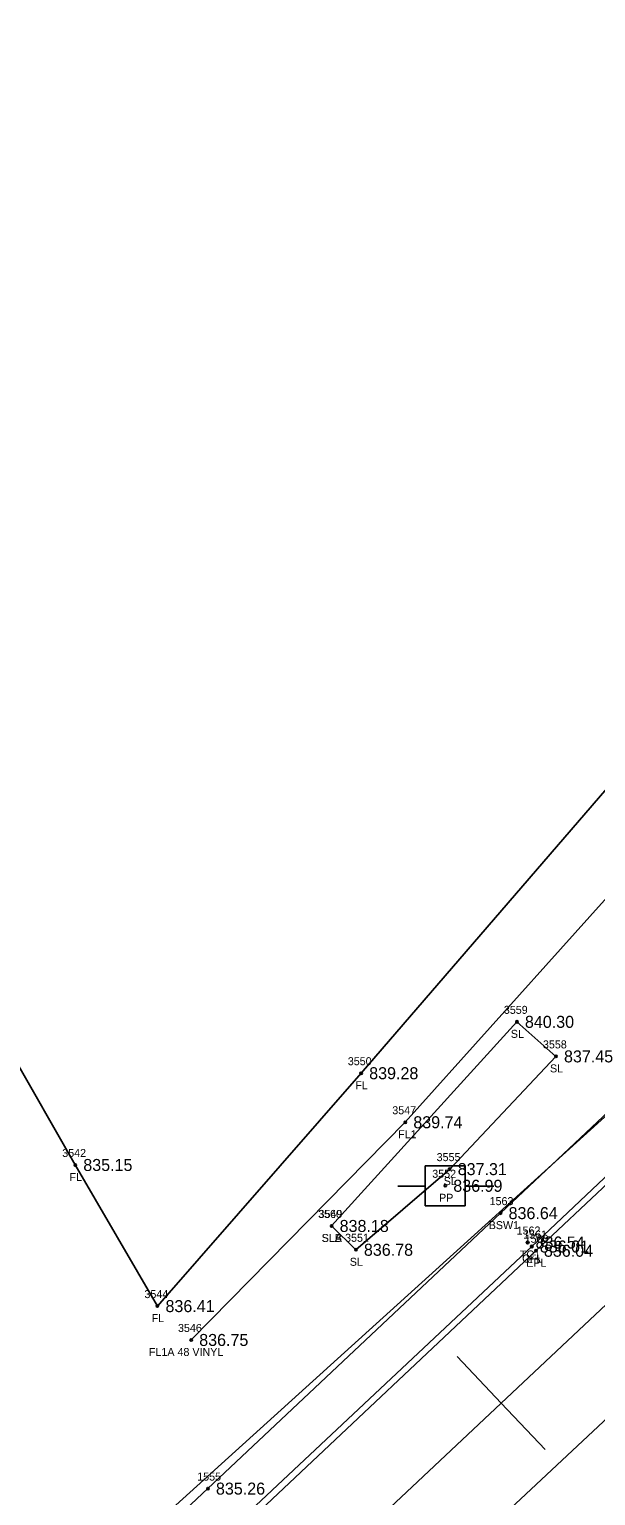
# Model space of a CAD drawing. Extents: x 1622501 to 1626664, y 1117816 to 1121579.
# Drawn here: x 1624658.9 to 1624729.6, y 1119930.4 to 1120113.7 of the extents above; entities that cross this region are included whole.
import ezdxf

# ---------------------------------------------------------------- set-up
doc = ezdxf.new("R2010")
doc.units = 0
for name, color, linetype in [('RD_EX_Conc', 7, 'Continuous'), ('RD_EX_Conc_txCode', 7, 'Continuous'), ('RD_EX_DR_Pipe', 7, 'Continuous'), ('RD_EX_Fence_Other', 7, 'Continuous'), ('RD_EX_Fence_Other_txCode', 7, 'Continuous'), ('RD_EX_Road', 7, 'Continuous'), ('RD_EX_Road_txCode', 7, 'Continuous'), ('RD_EX_TX_Conc_ELEV', 7, 'Continuous'), ('RD_EX_TX_Fence_Other_ELEV', 7, 'Continuous'), ('RD_EX_TX_Road_ELEV', 7, 'Continuous'), ('RD_EX_TX_VEG_ELEV', 7, 'Continuous'), ('RD_EX_UT', 7, 'Continuous'), ('RD_EX_UT_txCode', 7, 'Continuous'), ('RD_EX_VEG', 7, 'Continuous'), ('RD_EX_VEG_txCode', 7, 'Continuous'), ('RD_HC_Cl', 7, 'Continuous'), ('RD_HC_Data_Tic', 7, 'Continuous'), ('RD_HC_Survey_ELEV', 7, 'Continuous'), ('RD_SMD_Locator', 7, 'Continuous')]:
    doc.layers.add(name, color=color, linetype=linetype)

msp = doc.modelspace()

# ---------------------------------------------------------------- linework, layer by layer
at = {"layer": 'RD_EX_Conc'}
for points in [[(1624627.29, 1119872.79), (1624648.82, 1119893.33), (1624685.14, 1119927.24), (1624721.63, 1119961.54), (1624757.72, 1119995.68), (1624794.23, 1120030.2), (1624818.18, 1120052.72), (1624821.97, 1120057.48), (1624824.89, 1120062.27)], [(1624660.88, 1119912.17), (1624681.2, 1119931.28), (1624717.73, 1119965.71), (1624754.02, 1119999.93), (1624790.62, 1120034.43), (1624814.46, 1120056.83)]]:
    msp.add_lwpolyline(points, dxfattribs=at)
at = {"layer": 'RD_EX_DR_Pipe'}
msp.add_lwpolyline([(1625495.16, 1120700.17), (1625478.48, 1120693.94), (1625478.48, 1120693.94), (1625401.27, 1120618.61), (1625386.85, 1120595.89), (1625386.85, 1120595.89), (1625239.34, 1120454.58), (1625067.49, 1120292.51), (1624913.32, 1120147.08), (1624906.32, 1120142.58), (1624803.57, 1120043.73), (1624612.21, 1119870.34), (1624528.3, 1119793.12)], dxfattribs=at)
at = {"layer": 'RD_EX_Fence_Other'}
for points in [[(1624679.11, 1119949.86), (1624705.84, 1119977.07), (1624737.67, 1120012.59), (1624752.13, 1120029.37), (1624792.98, 1120063.53), (1624804.63, 1120073.99)], [(1624641.35, 1120014.22), (1624648.5, 1119999.9), (1624664.64, 1119971.73), (1624674.9, 1119954.09), (1624700.33, 1119983.2), (1624731.77, 1120019.72), (1624746.64, 1120034.86), (1624764.66, 1120053.21), (1624771.87, 1120060.24), (1624771.87, 1120060.24), (1624761.47, 1120072.27)]]:
    msp.add_lwpolyline(points, dxfattribs=at)
at = {"layer": 'RD_EX_Road'}
for points in [[(1624481.69, 1119706.57), (1624518.07, 1119740.62), (1624554.52, 1119774.63), (1624590.99, 1119808.78), (1624627.13, 1119843.17), (1624664.12, 1119876.78), (1624700.28, 1119911.28), (1624736.97, 1119945.68), (1624773.63, 1119979.8), (1624810.11, 1120014.45), (1624846.42, 1120048.91), (1624882.77, 1120083.19), (1624919.14, 1120117.14), (1624955.41, 1120151.75), (1624991.66, 1120186.11), (1625027.75, 1120220.09), (1625065.42, 1120252.96), (1625104.19, 1120284.12), (1625143.2, 1120315.04), (1625181.69, 1120345.9), (1625220.31, 1120377.13)], [(1624468.78, 1119721.97), (1624504.42, 1119755.42), (1624540.92, 1119789.52), (1624577, 1119823.63), (1624614.11, 1119858.36), (1624622.03, 1119866.66), (1624623.94, 1119868.41), (1624624.9, 1119868.05), (1624628.91, 1119871.9), (1624628.36, 1119872.68), (1624649.22, 1119892.43), (1624685.62, 1119926.57), (1624722.14, 1119961.01), (1624758.27, 1119995), (1624794.85, 1120029.55), (1624818.75, 1120051.93), (1624828.77, 1120068.77), (1624829.58, 1120080.91), (1624828.33, 1120088.31), (1624824.85, 1120095.34), (1624817.99, 1120105.91), (1624780.84, 1120159.39), (1624775.47, 1120165.89), (1624755.05, 1120187.38)]]:
    msp.add_lwpolyline(points, dxfattribs=at)
at = {"layer": 'RD_EX_UT'}
for p, q in [((1624713.32, 1119971.64), (1624708.32, 1119971.64)), ((1624708.32, 1119971.64), (1624708.32, 1119966.64)), ((1624713.32, 1119966.64), (1624713.32, 1119971.64)), ((1624704.89, 1119969.08), (1624708.36, 1119969.08)), ((1624713.25, 1119969.08), (1624716.89, 1119969.08)), ((1624708.32, 1119966.64), (1624713.32, 1119966.64))]:
    msp.add_line(p, q, dxfattribs=at)
at = {"layer": 'RD_EX_VEG'}
msp.add_lwpolyline([(1624696.64, 1119964.11), (1624699.67, 1119961.13), (1624711.38, 1119971.21), (1624724.65, 1119985.3), (1624719.77, 1119989.62), (1624696.64, 1119964.11)], dxfattribs=at)
at = {"layer": 'RD_HC_Cl'}
msp.add_line((1624678.65, 1119905.11), (1624870.49, 1120085.68), dxfattribs=at)
at = {"layer": 'RD_HC_Data_Tic'}
for q in [(1624712.33, 1119947.8), (1624723.3, 1119936.15)]:
    msp.add_line((1624717.81, 1119941.97), q, dxfattribs=at)
at = {"layer": 'RD_SMD_Locator'}
for centre in [(1624719.77, 1119989.62), (1624724.65, 1119985.3), (1624700.33, 1119983.2), (1624705.84, 1119977.07), (1624664.64, 1119971.73), (1624711.38, 1119971.21), (1624710.83, 1119969.13), (1624717.73, 1119965.71), (1624696.64, 1119964.11), (1624696.64, 1119964.11), (1624699.67, 1119961.13), (1624721.1, 1119962.04), (1624721.63, 1119961.54), (1624722.14, 1119961.01), (1624674.9, 1119954.09), (1624679.11, 1119949.86), (1624681.2, 1119931.28)]:
    msp.add_circle(centre, 0.15, dxfattribs=at)

# ---------------------------------------------------------------- texts
at = {"layer": 'RD_EX_Conc_txCode'}
for s, p in [('1563', (1624716.36, 1119966.71)), ('BSW1', (1624716.25, 1119963.71)), ('1562', (1624719.73, 1119963.04)), ('1561', (1624720.55, 1119962.54)), ('TC1', (1624720.14, 1119960.04)), ('CFL', (1624720.43, 1119959.54)), ('1555', (1624679.86, 1119932.28))]:
    msp.add_text(s, height=1, dxfattribs=at).set_placement(p)
at = {"layer": 'RD_EX_Fence_Other_txCode'}
for s, p in [('3550', (1624698.66, 1119984.2)), ('FL', (1624699.6, 1119981.2)), ('3547', (1624704.21, 1119978.07)), ('FL1', (1624704.94, 1119975.07)), ('3542', (1624663.01, 1119972.73)), ('FL', (1624663.91, 1119969.73)), ('3544', (1624673.27, 1119955.09)), ('FL', (1624674.17, 1119952.09)), ('3546', (1624677.46, 1119950.86)), ('FL1A 48 VINYL', (1624673.83, 1119947.86))]:
    msp.add_text(s, height=1, dxfattribs=at).set_placement(p)
at = {"layer": 'RD_EX_Road_txCode'}
for s, p in [('1560', (1624720.73, 1119962.01)), ('EPL', (1624720.94, 1119959.01))]:
    msp.add_text(s, height=1, dxfattribs=at).set_placement(p)
at = {"layer": 'RD_EX_TX_Conc_ELEV'}
for s, p in [('836.64', (1624718.73, 1119964.96)), ('836.54', (1624722.1, 1119961.29)), ('836.01', (1624722.63, 1119960.79)), ('835.26', (1624682.2, 1119930.53))]:
    msp.add_text(s, height=1.5, dxfattribs=at).set_placement(p)
at = {"layer": 'RD_EX_TX_Fence_Other_ELEV'}
for s, p in [('839.28', (1624701.33, 1119982.45)), ('839.74', (1624706.84, 1119976.32)), ('835.15', (1624665.64, 1119970.98)), ('836.41', (1624675.9, 1119953.34)), ('836.75', (1624680.11, 1119949.11))]:
    msp.add_text(s, height=1.5, dxfattribs=at).set_placement(p)
at = {"layer": 'RD_EX_TX_Road_ELEV'}
msp.add_text('836.04', height=1.5, dxfattribs=at).set_placement((1624723.14, 1119960.26))
at = {"layer": 'RD_EX_TX_VEG_ELEV'}
for s, p in [('840.30', (1624720.77, 1119988.87)), ('837.45', (1624725.65, 1119984.55)), ('837.31', (1624712.38, 1119970.46)), ('838.18', (1624697.64, 1119963.36)), ('838.18', (1624697.64, 1119963.36)), ('836.78', (1624700.67, 1119960.38))]:
    msp.add_text(s, height=1.5, dxfattribs=at).set_placement(p)
at = {"layer": 'RD_EX_UT_txCode'}
for s, p in [('3552', (1624709.2, 1119970.13)), ('PP', (1624710.05, 1119967.13))]:
    msp.add_text(s, height=1, dxfattribs=at).set_placement(p)
at = {"layer": 'RD_EX_VEG_txCode'}
for s, p in [('3559', (1624718.14, 1119990.62)), ('SL', (1624719.01, 1119987.62)), ('3558', (1624723.02, 1119986.3)), ('SL', (1624723.9, 1119983.3)), ('3555', (1624709.75, 1119972.21)), ('SL', (1624710.63, 1119969.21)), ('3560', (1624694.95, 1119965.11)), ('3549', (1624695.01, 1119965.11)), ('SLA', (1624695.39, 1119962.11)), ('SLB', (1624695.41, 1119962.11)), ('3551', (1624698.32, 1119962.13)), ('SL', (1624698.91, 1119959.13))]:
    msp.add_text(s, height=1, dxfattribs=at).set_placement(p)
at = {"layer": 'RD_HC_Survey_ELEV'}
msp.add_text('836.99', height=1.5, dxfattribs=at).set_placement((1624711.83, 1119968.38))

doc.saveas('drawing.dxf')
